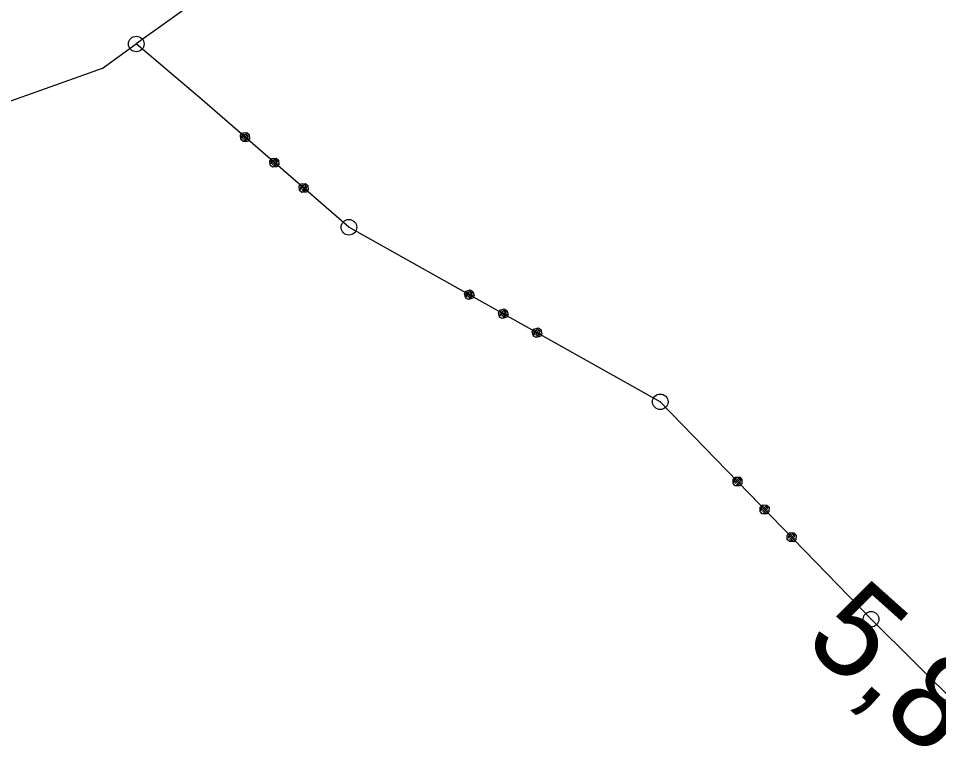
# Model space of a CAD drawing. Extents: x -866656 to -858817, y -1041816 to -1038653.
# Drawn here: x -864644.2 to -864585, y -1041373 to -1041325.9 of the extents above; entities that cross this region are included whole.
import ezdxf

# ---------------------------------------------------------------- set-up
doc = ezdxf.new("R2010")
doc.units = 0
for name, color, linetype in [('Vrstva 1', 7, 'Continuous'), ('Vrstva 3', 7, 'Continuous'), ('Vrstva 7', 7, 'Continuous')]:
    doc.layers.add(name, color=color, linetype=linetype)

msp = doc.modelspace()

# ---------------------------------------------------------------- linework, layer by layer
at = {"layer": 'Vrstva 1'}
for centre, radius in [((-864636.66, -1041327.58), 0.5), ((-864636.66, -1041327.58), 0.5), ((-864636.66, -1041327.58), 0.01), ((-864636.66, -1041327.58), 0.01), ((-864622.98, -1041339.37), 0.5), ((-864622.98, -1041339.37), 0.5), ((-864622.98, -1041339.37), 0.01), ((-864622.98, -1041339.37), 0.01), ((-864602.95, -1041350.6), 0.5), ((-864602.95, -1041350.6), 0.5), ((-864602.95, -1041350.6), 0.01), ((-864602.95, -1041350.6), 0.01), ((-864589.39, -1041364.59), 0.5), ((-864589.39, -1041364.59), 0.5), ((-864589.39, -1041364.59), 0.01), ((-864589.39, -1041364.59), 0.01)]:
    msp.add_circle(centre, radius, dxfattribs=at)
at = {"layer": 'Vrstva 3'}
for p, q in [((-864624.24, -1041318.67), (-864636.66, -1041327.58)), ((-864624.24, -1041318.67), (-864636.66, -1041327.58)), ((-864638.85, -1041329.15), (-864636.66, -1041327.58)), ((-864638.85, -1041329.15), (-864636.66, -1041327.58)), ((-864632.42, -1041331.18), (-864636.66, -1041327.58)), ((-864632.42, -1041331.18), (-864636.66, -1041327.58)), ((-864638.85, -1041329.15), (-864655.86, -1041335.25)), ((-864638.85, -1041329.15), (-864655.86, -1041335.25)), ((-864622.98, -1041339.37), (-864632.42, -1041331.18)), ((-864622.98, -1041339.37), (-864632.42, -1041331.18)), ((-864629.956, -1041333.45), (-864629.824, -1041333.299)), ((-864629.956, -1041333.45), (-864629.824, -1041333.299)), ((-864629.936, -1041333.732), (-864629.956, -1041333.45)), ((-864629.936, -1041333.732), (-864629.956, -1041333.45)), ((-864629.749, -1041333.364), (-864629.88, -1041333.515)), ((-864629.749, -1041333.364), (-864629.88, -1041333.515)), ((-864629.88, -1041333.515), (-864629.87, -1041333.656)), ((-864629.88, -1041333.515), (-864629.87, -1041333.656)), ((-864629.87, -1041333.656), (-864629.608, -1041333.354)), ((-864629.87, -1041333.656), (-864629.608, -1041333.354)), ((-864629.824, -1041333.299), (-864629.542, -1041333.279)), ((-864629.824, -1041333.299), (-864629.542, -1041333.279)), ((-864629.532, -1041333.42), (-864629.794, -1041333.722)), ((-864629.532, -1041333.42), (-864629.794, -1041333.722)), ((-864629.457, -1041333.485), (-864629.719, -1041333.787)), ((-864629.457, -1041333.485), (-864629.719, -1041333.787)), ((-864629.608, -1041333.354), (-864629.457, -1041333.485)), ((-864629.608, -1041333.354), (-864629.457, -1041333.485)), ((-864629.578, -1041333.777), (-864629.447, -1041333.626)), ((-864629.578, -1041333.777), (-864629.447, -1041333.626)), ((-864629.542, -1041333.279), (-864629.391, -1041333.41)), ((-864629.542, -1041333.279), (-864629.391, -1041333.41)), ((-864629.391, -1041333.41), (-864629.371, -1041333.692)), ((-864629.391, -1041333.41), (-864629.371, -1041333.692)), ((-864629.784, -1041333.863), (-864629.936, -1041333.732)), ((-864629.784, -1041333.863), (-864629.936, -1041333.732)), ((-864629.502, -1041333.843), (-864629.784, -1041333.863)), ((-864629.502, -1041333.843), (-864629.784, -1041333.863)), ((-864629.719, -1041333.787), (-864629.578, -1041333.777)), ((-864629.719, -1041333.787), (-864629.578, -1041333.777)), ((-864629.371, -1041333.692), (-864629.502, -1041333.843)), ((-864629.371, -1041333.692), (-864629.502, -1041333.843)), ((-864628.067, -1041335.088), (-864627.936, -1041334.937)), ((-864628.067, -1041335.088), (-864627.936, -1041334.937)), ((-864628.047, -1041335.37), (-864628.067, -1041335.088)), ((-864628.047, -1041335.37), (-864628.067, -1041335.088)), ((-864627.896, -1041335.501), (-864628.047, -1041335.37)), ((-864627.896, -1041335.501), (-864628.047, -1041335.37)), ((-864627.861, -1041335.002), (-864627.992, -1041335.153)), ((-864627.861, -1041335.002), (-864627.992, -1041335.153)), ((-864627.992, -1041335.153), (-864627.982, -1041335.295)), ((-864627.992, -1041335.153), (-864627.982, -1041335.295)), ((-864627.982, -1041335.295), (-864627.72, -1041334.992)), ((-864627.982, -1041335.295), (-864627.72, -1041334.992)), ((-864627.936, -1041334.937), (-864627.654, -1041334.917)), ((-864627.936, -1041334.937), (-864627.654, -1041334.917)), ((-864627.644, -1041335.058), (-864627.906, -1041335.36)), ((-864627.644, -1041335.058), (-864627.906, -1041335.36)), ((-864627.568, -1041335.123), (-864627.831, -1041335.426)), ((-864627.568, -1041335.123), (-864627.831, -1041335.426)), ((-864627.831, -1041335.426), (-864627.69, -1041335.416)), ((-864627.831, -1041335.426), (-864627.69, -1041335.416)), ((-864627.72, -1041334.992), (-864627.568, -1041335.123)), ((-864627.72, -1041334.992), (-864627.568, -1041335.123)), ((-864627.69, -1041335.416), (-864627.558, -1041335.265)), ((-864627.69, -1041335.416), (-864627.558, -1041335.265)), ((-864627.654, -1041334.917), (-864627.503, -1041335.048)), ((-864627.654, -1041334.917), (-864627.503, -1041335.048)), ((-864627.483, -1041335.33), (-864627.614, -1041335.481)), ((-864627.483, -1041335.33), (-864627.614, -1041335.481)), ((-864627.503, -1041335.048), (-864627.483, -1041335.33)), ((-864627.503, -1041335.048), (-864627.483, -1041335.33)), ((-864627.614, -1041335.481), (-864627.896, -1041335.501)), ((-864627.614, -1041335.481), (-864627.896, -1041335.501)), ((-864626.179, -1041336.726), (-864626.048, -1041336.575)), ((-864626.179, -1041336.726), (-864626.048, -1041336.575)), ((-864626.048, -1041336.575), (-864625.766, -1041336.555)), ((-864626.048, -1041336.575), (-864625.766, -1041336.555)), ((-864625.766, -1041336.555), (-864625.615, -1041336.686)), ((-864625.766, -1041336.555), (-864625.615, -1041336.686)), ((-864626.159, -1041337.008), (-864626.179, -1041336.726)), ((-864626.159, -1041337.008), (-864626.179, -1041336.726)), ((-864626.008, -1041337.139), (-864626.159, -1041337.008)), ((-864626.008, -1041337.139), (-864626.159, -1041337.008)), ((-864625.972, -1041336.641), (-864626.103, -1041336.792)), ((-864625.972, -1041336.641), (-864626.103, -1041336.792)), ((-864626.103, -1041336.792), (-864626.093, -1041336.933)), ((-864626.103, -1041336.792), (-864626.093, -1041336.933)), ((-864626.093, -1041336.933), (-864625.831, -1041336.631)), ((-864626.093, -1041336.933), (-864625.831, -1041336.631)), ((-864625.756, -1041336.696), (-864626.018, -1041336.998)), ((-864625.756, -1041336.696), (-864626.018, -1041336.998)), ((-864625.726, -1041337.119), (-864626.008, -1041337.139)), ((-864625.726, -1041337.119), (-864626.008, -1041337.139)), ((-864625.68, -1041336.762), (-864625.942, -1041337.064)), ((-864625.68, -1041336.762), (-864625.942, -1041337.064)), ((-864625.942, -1041337.064), (-864625.801, -1041337.054)), ((-864625.942, -1041337.064), (-864625.801, -1041337.054)), ((-864625.831, -1041336.631), (-864625.68, -1041336.762)), ((-864625.831, -1041336.631), (-864625.68, -1041336.762)), ((-864625.801, -1041337.054), (-864625.67, -1041336.903)), ((-864625.801, -1041337.054), (-864625.67, -1041336.903)), ((-864625.595, -1041336.968), (-864625.726, -1041337.119)), ((-864625.595, -1041336.968), (-864625.726, -1041337.119)), ((-864625.615, -1041336.686), (-864625.595, -1041336.968)), ((-864625.615, -1041336.686), (-864625.595, -1041336.968)), ((-864602.95, -1041350.6), (-864622.98, -1041339.37)), ((-864602.95, -1041350.6), (-864622.98, -1041339.37)), ((-864615.543, -1041343.654), (-864615.445, -1041343.479)), ((-864615.543, -1041343.654), (-864615.445, -1041343.479)), ((-864615.466, -1041343.926), (-864615.543, -1041343.654)), ((-864615.466, -1041343.926), (-864615.543, -1041343.654)), ((-864615.358, -1041343.528), (-864615.456, -1041343.702)), ((-864615.358, -1041343.528), (-864615.456, -1041343.702)), ((-864615.456, -1041343.702), (-864615.417, -1041343.839)), ((-864615.456, -1041343.702), (-864615.417, -1041343.839)), ((-864615.445, -1041343.479), (-864615.173, -1041343.402)), ((-864615.445, -1041343.479), (-864615.173, -1041343.402)), ((-864615.417, -1041343.839), (-864615.222, -1041343.49)), ((-864615.417, -1041343.839), (-864615.222, -1041343.49)), ((-864615.135, -1041343.539), (-864615.33, -1041343.887)), ((-864615.135, -1041343.539), (-864615.33, -1041343.887)), ((-864615.047, -1041343.587), (-864615.243, -1041343.936)), ((-864615.047, -1041343.587), (-864615.243, -1041343.936)), ((-864615.222, -1041343.49), (-864615.047, -1041343.587)), ((-864615.222, -1041343.49), (-864615.047, -1041343.587)), ((-864615.173, -1041343.402), (-864614.998, -1041343.5)), ((-864615.173, -1041343.402), (-864614.998, -1041343.5)), ((-864615.107, -1041343.898), (-864615.009, -1041343.724)), ((-864615.107, -1041343.898), (-864615.009, -1041343.724)), ((-864614.998, -1041343.5), (-864614.922, -1041343.772)), ((-864614.998, -1041343.5), (-864614.922, -1041343.772)), ((-864615.292, -1041344.024), (-864615.466, -1041343.926)), ((-864615.292, -1041344.024), (-864615.466, -1041343.926)), ((-864615.02, -1041343.947), (-864615.292, -1041344.024)), ((-864615.02, -1041343.947), (-864615.292, -1041344.024)), ((-864615.243, -1041343.936), (-864615.107, -1041343.898)), ((-864615.243, -1041343.936), (-864615.107, -1041343.898)), ((-864614.922, -1041343.772), (-864615.02, -1041343.947)), ((-864614.922, -1041343.772), (-864615.02, -1041343.947)), ((-864613.362, -1041344.876), (-864613.265, -1041344.702)), ((-864613.362, -1041344.876), (-864613.265, -1041344.702)), ((-864613.286, -1041345.148), (-864613.362, -1041344.876)), ((-864613.286, -1041345.148), (-864613.362, -1041344.876)), ((-864613.177, -1041344.751), (-864613.275, -1041344.925)), ((-864613.177, -1041344.751), (-864613.275, -1041344.925)), ((-864613.265, -1041344.702), (-864612.992, -1041344.625)), ((-864613.265, -1041344.702), (-864612.992, -1041344.625)), ((-864613.237, -1041345.061), (-864613.041, -1041344.712)), ((-864613.237, -1041345.061), (-864613.041, -1041344.712)), ((-864612.954, -1041344.761), (-864613.15, -1041345.11)), ((-864612.954, -1041344.761), (-864613.15, -1041345.11)), ((-864612.867, -1041344.81), (-864613.062, -1041345.159)), ((-864612.867, -1041344.81), (-864613.062, -1041345.159)), ((-864613.041, -1041344.712), (-864612.867, -1041344.81)), ((-864613.041, -1041344.712), (-864612.867, -1041344.81)), ((-864612.992, -1041344.625), (-864612.818, -1041344.723)), ((-864612.992, -1041344.625), (-864612.818, -1041344.723)), ((-864612.818, -1041344.723), (-864612.741, -1041344.995)), ((-864612.818, -1041344.723), (-864612.741, -1041344.995)), ((-864613.111, -1041345.246), (-864613.286, -1041345.148)), ((-864613.111, -1041345.246), (-864613.286, -1041345.148)), ((-864613.275, -1041344.925), (-864613.237, -1041345.061)), ((-864613.275, -1041344.925), (-864613.237, -1041345.061)), ((-864612.839, -1041345.17), (-864613.111, -1041345.246)), ((-864612.839, -1041345.17), (-864613.111, -1041345.246)), ((-864613.062, -1041345.159), (-864612.926, -1041345.121)), ((-864613.062, -1041345.159), (-864612.926, -1041345.121)), ((-864612.926, -1041345.121), (-864612.828, -1041344.946)), ((-864612.926, -1041345.121), (-864612.828, -1041344.946)), ((-864612.741, -1041344.995), (-864612.839, -1041345.17)), ((-864612.741, -1041344.995), (-864612.839, -1041345.17)), ((-864611.182, -1041346.099), (-864611.084, -1041345.924)), ((-864611.182, -1041346.099), (-864611.084, -1041345.924)), ((-864610.997, -1041345.973), (-864611.094, -1041346.148)), ((-864610.997, -1041345.973), (-864611.094, -1041346.148)), ((-864611.084, -1041345.924), (-864610.812, -1041345.848)), ((-864611.084, -1041345.924), (-864610.812, -1041345.848)), ((-864611.056, -1041346.284), (-864610.861, -1041345.935)), ((-864611.056, -1041346.284), (-864610.861, -1041345.935)), ((-864610.773, -1041345.984), (-864610.969, -1041346.333)), ((-864610.773, -1041345.984), (-864610.969, -1041346.333)), ((-864610.686, -1041346.033), (-864610.882, -1041346.382)), ((-864610.686, -1041346.033), (-864610.882, -1041346.382)), ((-864610.861, -1041345.935), (-864610.686, -1041346.033)), ((-864610.861, -1041345.935), (-864610.686, -1041346.033)), ((-864610.812, -1041345.848), (-864610.637, -1041345.945)), ((-864610.812, -1041345.848), (-864610.637, -1041345.945)), ((-864610.637, -1041345.945), (-864610.561, -1041346.218)), ((-864610.637, -1041345.945), (-864610.561, -1041346.218)), ((-864611.105, -1041346.371), (-864611.182, -1041346.099)), ((-864611.105, -1041346.371), (-864611.182, -1041346.099)), ((-864610.931, -1041346.469), (-864611.105, -1041346.371)), ((-864610.931, -1041346.469), (-864611.105, -1041346.371)), ((-864611.094, -1041346.148), (-864611.056, -1041346.284)), ((-864611.094, -1041346.148), (-864611.056, -1041346.284)), ((-864610.658, -1041346.392), (-864610.931, -1041346.469)), ((-864610.658, -1041346.392), (-864610.931, -1041346.469)), ((-864610.882, -1041346.382), (-864610.746, -1041346.343)), ((-864610.882, -1041346.382), (-864610.746, -1041346.343)), ((-864610.746, -1041346.343), (-864610.648, -1041346.169)), ((-864610.746, -1041346.343), (-864610.648, -1041346.169)), ((-864610.561, -1041346.218), (-864610.658, -1041346.392)), ((-864610.561, -1041346.218), (-864610.658, -1041346.392)), ((-864589.39, -1041364.59), (-864602.95, -1041350.6)), ((-864589.39, -1041364.59), (-864602.95, -1041350.6)), ((-864598.26, -1041355.582), (-864598.116, -1041355.443)), ((-864598.26, -1041355.582), (-864598.116, -1041355.443)), ((-864598.192, -1041355.795), (-864597.905, -1041355.517)), ((-864598.192, -1041355.795), (-864597.905, -1041355.517)), ((-864598.046, -1041355.514), (-864598.19, -1041355.654)), ((-864598.046, -1041355.514), (-864598.19, -1041355.654)), ((-864598.116, -1041355.443), (-864597.833, -1041355.447)), ((-864598.116, -1041355.443), (-864597.833, -1041355.447)), ((-864597.905, -1041355.517), (-864597.766, -1041355.66)), ((-864597.905, -1041355.517), (-864597.766, -1041355.66)), ((-864597.833, -1041355.447), (-864597.694, -1041355.591)), ((-864597.833, -1041355.447), (-864597.694, -1041355.591)), ((-864598.264, -1041355.865), (-864598.26, -1041355.582)), ((-864598.264, -1041355.865), (-864598.26, -1041355.582)), ((-864598.125, -1041356.008), (-864598.264, -1041355.865)), ((-864598.125, -1041356.008), (-864598.264, -1041355.865)), ((-864598.19, -1041355.654), (-864598.192, -1041355.795)), ((-864598.19, -1041355.654), (-864598.192, -1041355.795)), ((-864597.842, -1041356.013), (-864598.125, -1041356.008)), ((-864597.842, -1041356.013), (-864598.125, -1041356.008)), ((-864597.835, -1041355.588), (-864598.123, -1041355.867)), ((-864597.835, -1041355.588), (-864598.123, -1041355.867)), ((-864597.766, -1041355.66), (-864598.053, -1041355.939)), ((-864597.766, -1041355.66), (-864598.053, -1041355.939)), ((-864598.053, -1041355.939), (-864597.912, -1041355.941)), ((-864598.053, -1041355.939), (-864597.912, -1041355.941)), ((-864597.912, -1041355.941), (-864597.768, -1041355.802)), ((-864597.912, -1041355.941), (-864597.768, -1041355.802)), ((-864597.698, -1041355.873), (-864597.842, -1041356.013)), ((-864597.698, -1041355.873), (-864597.842, -1041356.013)), ((-864597.694, -1041355.591), (-864597.698, -1041355.873)), ((-864597.694, -1041355.591), (-864597.698, -1041355.873)), ((-864596.52, -1041357.377), (-864596.376, -1041357.238)), ((-864596.52, -1041357.377), (-864596.376, -1041357.238)), ((-864596.452, -1041357.59), (-864596.165, -1041357.312)), ((-864596.452, -1041357.59), (-864596.165, -1041357.312)), ((-864596.307, -1041357.309), (-864596.45, -1041357.449)), ((-864596.307, -1041357.309), (-864596.45, -1041357.449)), ((-864596.376, -1041357.238), (-864596.093, -1041357.242)), ((-864596.376, -1041357.238), (-864596.093, -1041357.242)), ((-864596.165, -1041357.312), (-864596.026, -1041357.455)), ((-864596.165, -1041357.312), (-864596.026, -1041357.455)), ((-864596.093, -1041357.242), (-864595.954, -1041357.386)), ((-864596.093, -1041357.242), (-864595.954, -1041357.386)), ((-864596.524, -1041357.66), (-864596.52, -1041357.377)), ((-864596.524, -1041357.66), (-864596.52, -1041357.377)), ((-864596.385, -1041357.803), (-864596.524, -1041357.66)), ((-864596.385, -1041357.803), (-864596.524, -1041357.66)), ((-864596.45, -1041357.449), (-864596.452, -1041357.59)), ((-864596.45, -1041357.449), (-864596.452, -1041357.59)), ((-864596.102, -1041357.808), (-864596.385, -1041357.803)), ((-864596.102, -1041357.808), (-864596.385, -1041357.803)), ((-864596.095, -1041357.384), (-864596.383, -1041357.662)), ((-864596.095, -1041357.384), (-864596.383, -1041357.662)), ((-864596.026, -1041357.455), (-864596.313, -1041357.734)), ((-864596.026, -1041357.455), (-864596.313, -1041357.734)), ((-864596.313, -1041357.734), (-864596.172, -1041357.736)), ((-864596.313, -1041357.734), (-864596.172, -1041357.736)), ((-864596.172, -1041357.736), (-864596.028, -1041357.597)), ((-864596.172, -1041357.736), (-864596.028, -1041357.597)), ((-864595.959, -1041357.669), (-864596.102, -1041357.808)), ((-864595.959, -1041357.669), (-864596.102, -1041357.808)), ((-864595.954, -1041357.386), (-864595.959, -1041357.669)), ((-864595.954, -1041357.386), (-864595.959, -1041357.669)), ((-864594.78, -1041359.172), (-864594.636, -1041359.033)), ((-864594.78, -1041359.172), (-864594.636, -1041359.033)), ((-864594.712, -1041359.385), (-864594.425, -1041359.107)), ((-864594.712, -1041359.385), (-864594.425, -1041359.107)), ((-864594.567, -1041359.105), (-864594.71, -1041359.244)), ((-864594.567, -1041359.105), (-864594.71, -1041359.244)), ((-864594.636, -1041359.033), (-864594.353, -1041359.037)), ((-864594.636, -1041359.033), (-864594.353, -1041359.037)), ((-864594.425, -1041359.107), (-864594.286, -1041359.25)), ((-864594.425, -1041359.107), (-864594.286, -1041359.25)), ((-864594.353, -1041359.037), (-864594.214, -1041359.181)), ((-864594.353, -1041359.037), (-864594.214, -1041359.181)), ((-864594.784, -1041359.455), (-864594.78, -1041359.172)), ((-864594.784, -1041359.455), (-864594.78, -1041359.172)), ((-864594.645, -1041359.598), (-864594.784, -1041359.455)), ((-864594.645, -1041359.598), (-864594.784, -1041359.455)), ((-864594.71, -1041359.244), (-864594.712, -1041359.385)), ((-864594.71, -1041359.244), (-864594.712, -1041359.385)), ((-864594.362, -1041359.603), (-864594.645, -1041359.598)), ((-864594.362, -1041359.603), (-864594.645, -1041359.598)), ((-864594.356, -1041359.179), (-864594.643, -1041359.457)), ((-864594.356, -1041359.179), (-864594.643, -1041359.457)), ((-864594.286, -1041359.25), (-864594.573, -1041359.529)), ((-864594.286, -1041359.25), (-864594.573, -1041359.529)), ((-864594.573, -1041359.529), (-864594.432, -1041359.531)), ((-864594.573, -1041359.529), (-864594.432, -1041359.531)), ((-864594.432, -1041359.531), (-864594.288, -1041359.392)), ((-864594.432, -1041359.531), (-864594.288, -1041359.392)), ((-864594.219, -1041359.464), (-864594.362, -1041359.603)), ((-864594.219, -1041359.464), (-864594.362, -1041359.603)), ((-864594.214, -1041359.181), (-864594.219, -1041359.464)), ((-864594.214, -1041359.181), (-864594.219, -1041359.464)), ((-864574.94, -1041378.96), (-864589.39, -1041364.59)), ((-864574.94, -1041378.96), (-864589.39, -1041364.59))]:
    msp.add_line(p, q, dxfattribs=at)

# ---------------------------------------------------------------- texts
at = {"layer": 'Vrstva 7'}
msp.add_text('5,8', height=6, rotation=318.15059, dxfattribs=at).set_placement((-864593.853, -1041366.15))

doc.saveas('drawing.dxf')
